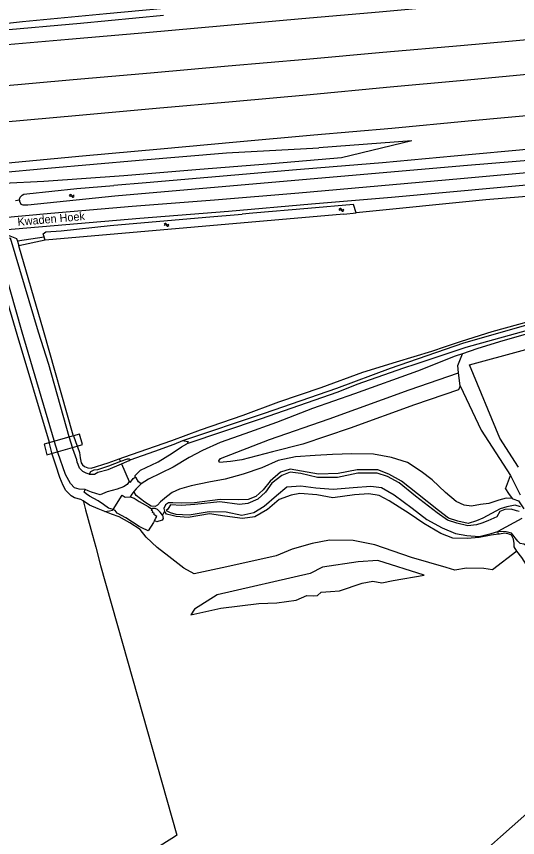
# Model space of a CAD drawing. Extents: x 126000 to 131009, y 393000 to 395500.
# Drawn here: x 129570 to 129724.5, y 394307.8 to 394560.9 of the extents above; entities that cross this region are included whole.
import ezdxf

# ---------------------------------------------------------------- set-up
doc = ezdxf.new("R2010")
doc.units = 0
for name, color, linetype in [('gg-anno-openbare ruimte label', 7, 'Continuous'), ('gg-knt-BGT kruinlijn', 7, 'Continuous'), ('gg-knt-verharding', 7, 'Continuous'), ('gg-kntw-bovenkant insteek waterloop', 7, 'Continuous'), ('gg-kntw-waterlijn', 7, 'Continuous'), ('gg-kwrk-duiker nz buis', 7, 'Continuous'), ('gg-kwrk-kunstwerk', 7, 'Continuous'), ('gg-kwrk-kunstwerk niveau 01', 7, 'Continuous'), ('gt-grn-groengrens', 7, 'Continuous'), ('gt-grn-vlakafsluiter', 7, 'Continuous'), ('gt-symb-watersymbool', 7, 'Continuous'), ('gx-grn-maaiveld', 7, 'Continuous')]:
    doc.layers.add(name, color=color, linetype=linetype)

# ---------------------------------------------------------------- blocks, each defined once
blk = doc.blocks.new('gt0-WA')
at = {"layer": 'gt-symb-watersymbool'}
for centre, start, end in [((-0.32, 0.02), 28.0725, 151.9275), ((0.43, 0.42), 208.0725, 331.9275), ((-0.32, -0.43), 28.0725, 151.9275), ((0.43, -0.03), 208.0725, 331.9275)]:
    blk.add_arc(centre, 0.425, start, end, dxfattribs=at)

msp = doc.modelspace()

# ---------------------------------------------------------------- linework, layer by layer
at = {"layer": 'gg-knt-BGT kruinlijn'}
for p, q in [((129615.29, 394561.19), (129589.69, 394558.71)), ((129589.69, 394558.71), (129563.67, 394556.39)), ((129634.77, 394518.84), (129663.18, 394520.45)), ((129691.9, 394522.58), (129663.18, 394520.45)), ((129607.79, 394516.65), (129634.77, 394518.84)), ((129579.63, 394514.11), (129607.79, 394516.65)), ((129551.43, 394511.49), (129579.63, 394514.11))]:
    msp.add_line(p, q, dxfattribs=at)
at = {"layer": 'gg-knt-verharding'}
for points in [[(129873.64, 394523.74), (129871.21, 394523.58), (129844.18, 394521.66), (129818.24, 394520.06), (129784.19, 394517.78), (129759.3, 394515.64), (129732.93, 394513.22), (129706.88, 394510.89), (129657.07, 394506.47), (129631.07, 394504.29), (129605.65, 394502.27), (129580.54, 394500.13), (129564.82, 394498.74)], [(129873.39, 394519.87), (129836.6, 394517.3), (129810.32, 394515.65), (129784.11, 394513.89), (129758.59, 394511.72), (129736.18, 394509.71), (129685.62, 394505.1), (129660.98, 394503.02), (129635.31, 394500.73), (129608.05, 394498.61), (129566.02, 394494.97)]]:
    msp.add_lwpolyline(points, dxfattribs=at)
at = {"layer": 'gg-kntw-bovenkant insteek waterloop'}
for p, q in [((129670.95, 394500), (129674.72, 394500.32)), ((129670.95, 394500), (129578.8, 394491.97)), ((129587.48, 394431.8), (129587.55, 394431.62)), ((129580.99, 394425.95), (129580.04, 394429.62)), ((129588.71, 394428.47), (129588.8, 394428.24))]:
    msp.add_line(p, q, dxfattribs=at)
for points in [[(129600.28, 394505.58), (129707.76, 394514.95), (129762.81, 394519.5), (129866.46, 394526.61), (129873.86, 394527.18)], [(129674.72, 394500.32), (129673.91, 394502.92), (129659.84, 394501.66), (129642.89, 394500.3), (129639.53, 394500)], [(129578.8, 394491.97), (129578.24, 394493.84), (129579.01, 394494.53), (129583.73, 394494.81), (129598.84, 394496.45), (129628.4, 394498.99), (129639.53, 394500)], [(129566.37, 394493.88), (129570.01, 394492.4), (129570.25, 394491.58)], [(129570.25, 394491.58), (129570.65, 394490.21), (129570.65, 394490.2)], [(129587.48, 394431.8), (129578.28, 394464.11), (129570.65, 394490.2)], [(129562.66, 394487.71), (129570.03, 394462.96), (129580.04, 394429.62)]]:
    msp.add_lwpolyline(points, dxfattribs=at)
at = {"layer": 'gg-kntw-waterlijn'}
for p, q in [((129786.55, 394480.58), (129708.55, 394458.81)), ((129708.55, 394458.81), (129693.14, 394453.7)), ((129582.74, 394426.46), (129581.6, 394430.08)), ((129586.15, 394431.41), (129587.28, 394427.79))]:
    msp.add_line(p, q, dxfattribs=at)
for points in [[(129581.6, 394430.08), (129581.56, 394430.2), (129571.69, 394463.6), (129564.19, 394489.7), (129563.81, 394491.03), (129564.47, 394491.66), (129563.97, 394493.11)], [(129566.37, 394493.88), (129566.76, 394492.6), (129568.05, 394492.67), (129576.67, 394463.69), (129579.83, 394453.7), (129586.15, 394431.41)], [(129685.28, 394452.43), (129707.94, 394460.27), (129750.46, 394472.39), (129787.74, 394482.46), (129788.27, 394481.07), (129786.55, 394480.58)]]:
    msp.add_lwpolyline(points, dxfattribs=at)
at = {"layer": 'gg-kwrk-duiker nz buis'}
msp.add_line((129578.52, 394492.9), (129570.25, 394491.58), dxfattribs=at)
at = {"layer": 'gg-kwrk-kunstwerk'}
msp.add_lwpolyline([(129588.71, 394428.47), (129590.32, 394428.94), (129589.4, 394432.14), (129587.55, 394431.62)], dxfattribs=at)
at = {"layer": 'gg-kwrk-kunstwerk niveau 01'}
for p in [(129587.55, 394431.62), (129579.38, 394425.75)]:
    msp.add_line(p, (129588.71, 394428.47), dxfattribs=at)
msp.add_lwpolyline([(129587.55, 394431.62), (129578.5, 394429.06), (129579.38, 394425.75)], dxfattribs=at)
at = {"layer": 'gt-grn-groengrens'}
msp.add_line((129578.8, 394491.97), (129570.65, 394490.2), dxfattribs=at)
at = {"layer": 'gt-grn-vlakafsluiter'}
for p, q in [((129720.79, 394415.23), (129722.3, 394419.42)), ((129722.3, 394419.42), (129725.24, 394413.45))]:
    msp.add_line(p, q, dxfattribs=at)
at = {"layer": 'gx-grn-maaiveld'}
for p, q in [((129570.91, 394504.3), (129569.62, 394504.07)), ((129706.72, 394447.01), (129706.28, 394451.08)), ((129601.62, 394424.56), (129602.01, 394423.67)), ((129602.33, 394422.95), (129604.72, 394417.52)), ((129615.66, 394408.41), (129615.02, 394407.14)), ((129725.78, 394406.11), (129718.43, 394402.13)), ((129718.64, 394401.26), (129718.43, 394402.13)), ((129724.29, 394396.1), (129723.38, 394397.4))]:
    msp.add_line(p, q, dxfattribs=at)
for points in [[(129489.45, 394545.49), (129514.15, 394547.64), (129538.16, 394549.73), (129562.22, 394551.83), (129585.99, 394553.89), (129609.88, 394555.94), (129633.89, 394558.09), (129657.94, 394560.26), (129681.84, 394562.33), (129705.59, 394564.49), (129729.59, 394566.68), (129753.45, 394568.78), (129777, 394570.88), (129801.54, 394573.02), (129825.36, 394575.37), (129849.17, 394577.59), (129862.85, 394578.94)], [(129488.96, 394551.97), (129502.26, 394553.07), (129525.39, 394555.01), (129546.92, 394556.61), (129571.8, 394559.33), (129597.72, 394561.82), (129621.07, 394564), (129647.99, 394566.35), (129674.03, 394568.64), (129700.75, 394570.91), (129728.94, 394573.66), (129759.68, 394576.29), (129766.21, 394574.8)], [(129490.41, 394532.95), (129515.68, 394535.26), (129539.55, 394537.23), (129563.35, 394539.26), (129587.5, 394541.49), (129611.29, 394543.49), (129635.23, 394545.73), (129659.25, 394547.77), (129682.95, 394549.87), (129706.9, 394551.99), (129730.93, 394554.13), (129754.65, 394556.18), (129778.77, 394558.3), (129804.09, 394560.55)], [(129865.31, 394555.86), (129850.33, 394554.46), (129826.6, 394552.21), (129802.81, 394549.97), (129779.17, 394547.81), (129755.54, 394545.62), (129731.72, 394543.4), (129707.93, 394541.18), (129684.07, 394538.96), (129660.51, 394536.78), (129636.62, 394534.63), (129613.04, 394532.48), (129589.25, 394530.34), (129565.21, 394528.16), (129541.7, 394526.15), (129517.59, 394523.97), (129491.27, 394521.64)], [(129492.23, 394509.09), (129518.53, 394511.47), (129543.02, 394513.62), (129567.43, 394515.8), (129590.31, 394517.93), (129614.37, 394520.05), (129637.78, 394522.25), (129661.62, 394524.37), (129685.68, 394526.47), (129709.24, 394528.71), (129732.82, 394530.9), (129756.85, 394533.14), (129780.62, 394535.31), (129804.43, 394537.49), (129827.65, 394539.52), (129851.77, 394541.91), (129866.66, 394543.23)], [(129868.05, 394530.23), (129829.6, 394527.45), (129780.31, 394524.49), (129755.99, 394522.74), (129729.44, 394520.13), (129704.92, 394517.82), (129682.85, 394515.82), (129667.66, 394514.54), (129656.34, 394513.59), (129609.99, 394509.66), (129600.04, 394508.83)], [(129691.9, 394522.58), (129670.2, 394517.34), (129648.64, 394515.46), (129626.5, 394513.74), (129603.11, 394511.78), (129578.36, 394510.03), (129566.01, 394509.41), (129557.7, 394508.54), (129548.78, 394507.18), (129531.91, 394505.71), (129513.3, 394504.53), (129501.04, 394505.08)], [(129570.91, 394504.3), (129570.91, 394504.59), (129571.15, 394505.16), (129571.69, 394505.85), (129572.27, 394506.1), (129573.19, 394506.25), (129588.55, 394507.89), (129600.04, 394508.83)], [(129774.16, 394508.87), (129771.33, 394509.01), (129714.65, 394504.34), (129674.72, 394500.32)], [(129570.91, 394504.3), (129570.93, 394503.92), (129571.3, 394503.08), (129571.93, 394502.88), (129573.49, 394502.79), (129600.28, 394505.58)], [(129601.62, 394424.56), (129603.12, 394425.09), (129612.8, 394428.46), (129617.89, 394430.23), (129626.68, 394433.51), (129639.83, 394437.99), (129650.9, 394442.07), (129663.87, 394446.52), (129676.74, 394451.21), (129687.18, 394454.47), (129698.05, 394457.7), (129702.27, 394459.17), (129707.22, 394460.83), (129716.66, 394463.79), (129736.05, 394469.1), (129745.13, 394472.03), (129771.77, 394479.23), (129784.05, 394482.9), (129785.96, 394483.29)], [(129785.96, 394483.29), (129788.6, 394483.84), (129789.66, 394483.81), (129791.28, 394483.49), (129791.65, 394483.25), (129791.61, 394482.82), (129791.31, 394482.12), (129790.25, 394480.63), (129786.73, 394479.26), (129776.07, 394476.36), (129766.74, 394473.78), (129757.71, 394471.31), (129748.59, 394468.47), (129740.5, 394466.56), (129727.86, 394463.17), (129718.95, 394460.62), (129711.87, 394458.41), (129707.49, 394456.91)], [(129724.76, 394421.98), (129719.05, 394430.94), (129709.62, 394453.54), (129791.92, 394475.92), (129796.8, 394478.12), (129799.04, 394478.39)], [(129707.49, 394456.91), (129705.22, 394456.13), (129693.58, 394451.52), (129674.21, 394444.59), (129661.23, 394440.08), (129650.16, 394435.73), (129640.37, 394432.22), (129632.8, 394429.56), (129627.3, 394427.13), (129623.2, 394424.93), (129618.29, 394421.95), (129610.72, 394418.29), (129608.38, 394416.85)], [(129706.28, 394451.08), (129706.04, 394453.28), (129707.49, 394456.91)], [(129621.28, 394430.21), (129646.42, 394438.57), (129668.72, 394446.35), (129685.28, 394452.43)], [(129693.14, 394453.7), (129689.31, 394452.47), (129674.92, 394447.4), (129669.02, 394445.05), (129645.09, 394436.74), (129622.52, 394429.19)], [(129706.72, 394447.01), (129706.21, 394445.81), (129692.68, 394441.21), (129672.84, 394434.03), (129658.23, 394429.03), (129648.87, 394426.72), (129639.46, 394424.22), (129636.01, 394423.71), (129632.55, 394423.43), (129632.4, 394423.87), (129632.83, 394424.66), (129647.99, 394430.46), (129666.41, 394436.84), (129691.09, 394445.77), (129706.28, 394451.08)], [(129706.72, 394447.01), (129713.26, 394433.37), (129722.3, 394419.42)], [(129605.02, 394424.17), (129612.61, 394426.92), (129618.55, 394429.02), (129621.25, 394430.22), (129621.28, 394430.21)], [(129621.28, 394430.21), (129621.65, 394430.08), (129622.95, 394429.89), (129622.56, 394429.22), (129622.52, 394429.19)], [(129592.34, 394419.84), (129591.49, 394420.1), (129590.43, 394420.62), (129589.43, 394421.68), (129589.04, 394422.73), (129588.67, 394423.49), (129588.59, 394424.25), (129587.33, 394427.63), (129587.28, 394427.79)], [(129588.8, 394428.24), (129589.39, 394426.51), (129589.64, 394424.84), (129589.95, 394423.32), (129590.28, 394422.67), (129590.94, 394422.15), (129592, 394421.76), (129592.95, 394421.66), (129598.2, 394423.34), (129601.62, 394424.56)], [(129606.61, 394418.91), (129606.58, 394419.41), (129608.21, 394421.02), (129613.45, 394423.51), (129613.66, 394423.64), (129617.93, 394426.28), (129620.88, 394428.21), (129622.52, 394429.19)], [(129590.5, 394411.59), (129589.84, 394412.04), (129587.89, 394412.47), (129586.88, 394413.17), (129585.18, 394414.76), (129584.39, 394416.29), (129583.37, 394418.77), (129582.12, 394422.61), (129580.99, 394425.95)], [(129591.19, 394415.08), (129589.29, 394415.22), (129587.85, 394415.57), (129586.67, 394416.88), (129585.06, 394419.74), (129582.74, 394426.46)], [(129605.02, 394424.17), (129604.71, 394424.45), (129604.11, 394424.46), (129602.01, 394423.67)], [(129602.33, 394422.95), (129604.75, 394423.98), (129605.02, 394424.17)], [(129722.76, 394412.26), (129720.98, 394412.45), (129718.65, 394411.82), (129715.63, 394410.71), (129713.05, 394410.41), (129710.23, 394409.91), (129708, 394410.27), (129705.56, 394411.41), (129702.2, 394414.12), (129698.13, 394418.05), (129694.73, 394420.64), (129690.53, 394423.36), (129685.55, 394424.91), (129680.03, 394425.93), (129673.42, 394426.03), (129667.39, 394425.91), (129662.09, 394425.58), (129655.97, 394425.11), (129650.69, 394424.05), (129645.67, 394421.79), (129639.91, 394419.75), (129634.29, 394418.24), (129629.32, 394417.34), (129623.84, 394416.16), (129620.19, 394415.13), (129617.99, 394414.11), (129616.18, 394412.82), (129614.34, 394411.29), (129613.47, 394410.2), (129612.73, 394409.82), (129611.46, 394409.9), (129609.51, 394411.16), (129606.83, 394413.25), (129606.14, 394414.45)], [(129602.01, 394423.67), (129598.32, 394422.28), (129594.91, 394421.13), (129593.8, 394421.05), (129592.83, 394420.52), (129592.34, 394419.84)], [(129592.34, 394419.84), (129594.01, 394419.83), (129595.07, 394420.45), (129598.26, 394421.21), (129602.33, 394422.95)], [(129725.36, 394409.74), (129723.73, 394410.23), (129721.15, 394409.7), (129719.11, 394409.11), (129716.4, 394407.65), (129713.79, 394406.19), (129711.77, 394405.39), (129709.2, 394404.56), (129706.06, 394405.36), (129703.2, 394406.24), (129700.04, 394408.59), (129693.66, 394413.76), (129688.73, 394417.68), (129684.77, 394419.85), (129681.43, 394421.12), (129675.05, 394421.14), (129669.11, 394419.96), (129663.1, 394419.78), (129657.83, 394420.71), (129654.31, 394421.3), (129651.39, 394420.44), (129648.16, 394417.61), (129646.03, 394414.97), (129643.72, 394412.96), (129641.42, 394411.98), (129638.52, 394411.94), (129632.75, 394411.96), (129624.9, 394410.96), (129620.85, 394410.85), (129618.13, 394410.93), (129616.8, 394410.97), (129615.92, 394410.34), (129615.45, 394409.22), (129615.66, 394408.41)], [(129725.01, 394408.3), (129724.17, 394408.5), (129722.53, 394408.99), (129720.58, 394408.94), (129718.97, 394408.28), (129718.11, 394406.61), (129715.28, 394405.38), (129713.44, 394404.73), (129711.77, 394404.2), (129709.1, 394403.9), (129705.7, 394404.65), (129702.84, 394405.66), (129699.72, 394407.85), (129693, 394412.99), (129687.93, 394417.11), (129684.38, 394419.08), (129681.14, 394420.1), (129675.2, 394420.09), (129668.99, 394418.78), (129662.78, 394418.82), (129657.63, 394420.05), (129654.4, 394420.4), (129651.81, 394419.44), (129648.74, 394416.99), (129646.76, 394414.3), (129644.37, 394412.06), (129641.35, 394410.73), (129638.7, 394410.5), (129632.7, 394411.32), (129624.97, 394410.49), (129620.9, 394410.1), (129617.5, 394410.3), (129617.22, 394410.08), (129616.62, 394409), (129616.17, 394408.6), (129617.32, 394407.95), (129619.09, 394407.46), (129623.19, 394407.26), (129629.35, 394408.29), (129634.6, 394408.22), (129639.47, 394407.21), (129643.13, 394407.98), (129646.32, 394409.96), (129650.14, 394413.27), (129653.31, 394415.86), (129657.64, 394416.18), (129662.26, 394415.63), (129667.59, 394415.16), (129673.73, 394415.72), (129679.22, 394416.13), (129682.5, 394415.73), (129686.41, 394413.42), (129692.02, 394409.34), (129696.51, 394405.86), (129701.24, 394403.21), (129705.3, 394401.46), (129708.86, 394400.87), (129712.63, 394400.59), (129716.28, 394401.46), (129718.43, 394402.13)], [(129604.72, 394417.52), (129604.06, 394416.62), (129603.01, 394415.9), (129601.04, 394415.21), (129597.94, 394414.31), (129595.77, 394413.45), (129593.12, 394414.27), (129592.11, 394414.66), (129591.19, 394415.08)], [(129604.72, 394417.52), (129605.11, 394417.31), (129605.95, 394418.47), (129606.61, 394418.91)], [(129608.38, 394416.85), (129607.28, 394415.69), (129606.92, 394415.31), (129606.14, 394414.45)], [(129608.38, 394416.85), (129607.56, 394417.46), (129606.85, 394418.67), (129606.61, 394418.91)], [(129599.82, 394408.91), (129598.38, 394409.31), (129596.83, 394410.41), (129595.18, 394411.61), (129592.51, 394413), (129591.45, 394413.74), (129590.86, 394414.3), (129591.19, 394415.08)], [(129606.14, 394414.45), (129605.51, 394413.62), (129604.99, 394412.77)], [(129720.79, 394415.23), (129721.69, 394413.87), (129722.76, 394412.26)], [(129590.5, 394411.59), (129590.59, 394411.29), (129591.26, 394408.8), (129592.87, 394402.89), (129594.39, 394397.3), (129595.92, 394391.67), (129602.68, 394367.74), (129619.41, 394308.52), (129618.67, 394308.05), (129469.13, 394214.33), (129366.26, 394150.4), (129257.8, 394082.16)], [(129597.19, 394408.29), (129595.16, 394409.08), (129592.49, 394410.26), (129590.5, 394411.59)], [(129599.82, 394408.91), (129602.52, 394413.31), (129603.44, 394412.7), (129604.99, 394412.77)], [(129604.99, 394412.77), (129606.29, 394412.43), (129607.77, 394411.4), (129610.55, 394409.79), (129611.62, 394409.09)], [(129718.64, 394401.26), (129716.34, 394401.02), (129712.63, 394400.26), (129708.91, 394400), (129704.47, 394400.12), (129700.78, 394401.54), (129695.56, 394404.6), (129691.09, 394407.71), (129684.88, 394411.63), (129681.79, 394413.22), (129678.64, 394413.7), (129674.2, 394413.41), (129667.52, 394412.51), (129662.57, 394413.38), (129657.33, 394413.81), (129654.66, 394413.32), (129651, 394411.98), (129647.36, 394408.95), (129643.42, 394406.68), (129639.61, 394406.1), (129634.23, 394406.82), (129629.5, 394407.56), (129622.91, 394406.42), (129619.24, 394406.76), (129617.96, 394407.03), (129616.26, 394407.46), (129615.66, 394408.41)], [(129722.76, 394412.26), (129723.06, 394412.23), (129724.8, 394411.58), (129726.37, 394409.1)], [(129615.02, 394407.14), (129614.3, 394408.08), (129613.45, 394408.93), (129612.77, 394409.23), (129611.94, 394409.23), (129611.62, 394409.09)], [(129612.56, 394405.5), (129612.96, 394406.21), (129613.25, 394406.72), (129612.28, 394407.32), (129612.49, 394407.65), (129611.95, 394408), (129612.03, 394408.39), (129611.65, 394408.62), (129611.85, 394408.95), (129611.62, 394409.09)], [(129597.19, 394408.29), (129598.66, 394408.46), (129599.62, 394408.75), (129599.82, 394408.91)], [(129724.29, 394396.1), (129716.71, 394390.28), (129714.04, 394390.75), (129708.77, 394390.8), (129705.11, 394390.24), (129702.5, 394390.99), (129691.81, 394394.07), (129680.44, 394397.97), (129673.75, 394399.36), (129666.48, 394399.49), (129661.19, 394398.47), (129654.97, 394396.68), (129650.01, 394394.63), (129634.79, 394391.26), (129624.76, 394389.03), (129621.62, 394390.78), (129616.91, 394394.37), (129613.39, 394397.23), (129609.93, 394400.41), (129608.08, 394402.77), (129604.91, 394404.76), (129601.59, 394406.67), (129599.24, 394407.47), (129597.19, 394408.29)], [(129612.56, 394405.5), (129612.23, 394404.85), (129610.61, 394402.37), (129608.59, 394403.3), (129607.75, 394403.68), (129603.67, 394406.29), (129601.03, 394407.79), (129600.36, 394408.64), (129599.82, 394408.91)], [(129615.02, 394407.14), (129615.24, 394406.13), (129614.87, 394405.64), (129613.27, 394405.15), (129612.56, 394405.5)], [(129731.28, 394388.68), (129730.84, 394389.65), (129730.96, 394390.37), (129733.46, 394391.92), (129733.03, 394392.45), (129731.1, 394394.44), (129729.74, 394396.47), (129728.22, 394397.1), (129726.41, 394398.25), (129725.25, 394398.39), (129724.53, 394399.17), (129722.6, 394401.61), (129720.94, 394402.06), (129718.43, 394402.13)], [(129723.38, 394397.4), (129723.42, 394398.39), (129723.2, 394399.73), (129722.57, 394400.99), (129721.93, 394401.3), (129720.55, 394401.61), (129718.9, 394401.28), (129718.64, 394401.26)], [(129755.48, 394348.14), (129736.14, 394378.86), (129730.93, 394386.46), (129729.37, 394388.7), (129727.75, 394391.02), (129725.77, 394394.14), (129724.29, 394396.1)], [(129675.3, 394392.73), (129664.29, 394391.09), (129660.48, 394389.19), (129631.8, 394382.57), (129624.81, 394378.23), (129623.7, 394376.43), (129632.94, 394378.46), (129644.71, 394379.98), (129650.27, 394380.18), (129656.22, 394380.97), (129659.48, 394382.39), (129661.46, 394382.27), (129662.81, 394382.35), (129663.92, 394383.42), (129666.78, 394383.58), (129669.56, 394383.82), (129676.54, 394386.2), (129679.88, 394386.83), (129682.65, 394386.28), (129686.15, 394387.03), (129695.71, 394388.67), (129681.43, 394393.21), (129675.3, 394392.73)], [(129758.8, 394343.41), (129750.72, 394336.14), (129733.64, 394320.78), (129719.23, 394308), (129697.93, 394289.11), (129687.68, 394280.02), (129663.27, 394258.47), (129658.14, 394253.93), (129656.55, 394252.53), (129654.53, 394250.74), (129601.59, 394204.01), (129519.27, 394131.33), (129420.18, 394043.85), (129359.79, 393990.53), (129266.43, 393908.11), (129212.84, 393860.79), (129204.23, 393853.19)]]:
    msp.add_lwpolyline(points, dxfattribs=at)

# ---------------------------------------------------------------- block references
at = {"layer": 'gt-symb-watersymbool'}
for p, rotation in [((129586.96, 394505.58), 5.163306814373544), ((129670.11, 394501.28), 5.163306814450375), ((129616.18, 394496.66), 4.99208116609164)]:
    msp.add_blockref('gt0-WA', p, dxfattribs=dict(at, rotation=rotation))

# ---------------------------------------------------------------- texts
at = {"layer": 'gg-anno-openbare ruimte label'}
msp.add_text('Kwaden Hoek', height=2.5, rotation=5.1, dxfattribs=at).set_placement((129570.4, 394496.32))

doc.saveas('drawing.dxf')
